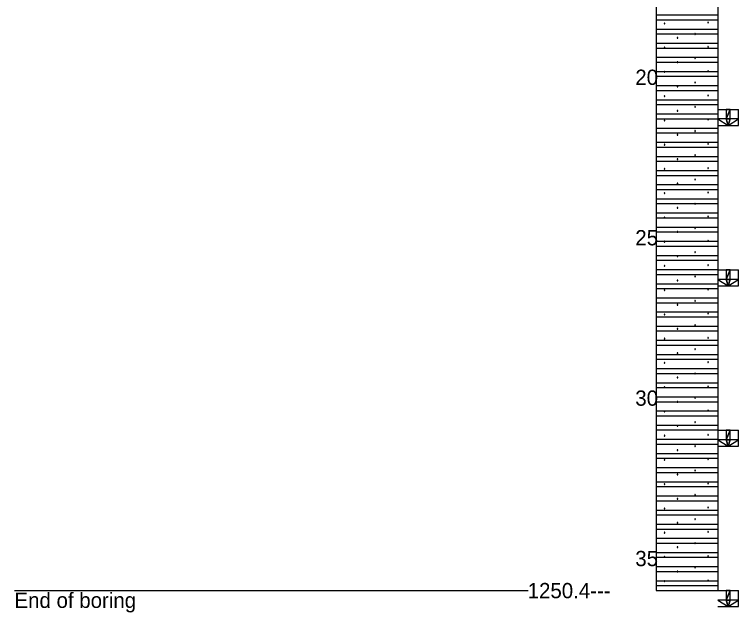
# Model space of a CAD drawing. Extents: x -2 to 138, y 24 to 58.
# Drawn here: x 27.88 to 33.76, y 39.39 to 44.24 of the extents above; entities that cross this region are included whole.
import ezdxf

# ---------------------------------------------------------------- set-up
doc = ezdxf.new("R2010")
doc.units = 0

msp = doc.modelspace()

# ---------------------------------------------------------------- linework, layer by layer
for points in [[(33.0889, 48.9382), (33.0889, 39.5632)], [(33.5889, 48.9382), (33.5889, 39.5632)], [(33.0889, 44.2363), (33.5889, 44.2363)], [(33.0889, 44.197), (33.5889, 44.197)], [(33.1593, 44.1672), (33.1577, 44.17), (33.1544, 44.17), (33.1528, 44.1672), (33.1544, 44.1643), (33.1577, 44.1643), (33.1593, 44.1672)], [(33.5121, 44.1737), (33.5104, 44.1766), (33.5072, 44.1766), (33.5055, 44.1737), (33.5072, 44.1709), (33.5104, 44.1709), (33.5121, 44.1737)], [(33.0889, 44.1215), (33.5889, 44.1215)], [(33.0889, 44.0821), (33.5889, 44.0821)], [(33.264, 44.0493), (33.2623, 44.0522), (33.2591, 44.0522), (33.2574, 44.0493), (33.2591, 44.0465), (33.2623, 44.0465), (33.264, 44.0493)], [(33.4066, 44.0812), (33.4049, 44.084), (33.4016, 44.084), (33.4, 44.0812), (33.4016, 44.0783), (33.4049, 44.0783), (33.4066, 44.0812)], [(33.0889, 44.0067), (33.5889, 44.0067)], [(33.5121, 43.9768), (33.5104, 43.9797), (33.5072, 43.9797), (33.5055, 43.9768), (33.5072, 43.974), (33.5104, 43.974), (33.5121, 43.9768)], [(33.0889, 43.9673), (33.5889, 43.9673)], [(33.1593, 43.9703), (33.1577, 43.9732), (33.1544, 43.9732), (33.1528, 43.9703), (33.1544, 43.9674), (33.1577, 43.9674), (33.1593, 43.9703)], [(33.0889, 43.8919), (33.5889, 43.8919)], [(33.4066, 43.8843), (33.4049, 43.8871), (33.4016, 43.8871), (33.4, 43.8843), (33.4016, 43.8815), (33.4049, 43.8815), (33.4066, 43.8843)], [(33.0889, 43.8525), (33.5889, 43.8525)], [(33.264, 43.8524), (33.2623, 43.8553), (33.2591, 43.8553), (33.2574, 43.8525), (33.2591, 43.8496), (33.2623, 43.8496), (33.264, 43.8524)], [(33.0889, 43.777), (33.5889, 43.777)], [(33.1593, 43.7735), (33.1577, 43.7763), (33.1544, 43.7763), (33.1528, 43.7735), (33.1544, 43.7706), (33.1577, 43.7706), (33.1593, 43.7735)], [(33.5121, 43.78), (33.5104, 43.7829), (33.5072, 43.7829), (33.5055, 43.78), (33.5072, 43.7772), (33.5104, 43.7772), (33.5121, 43.78)], [(33.0889, 43.7377), (33.5889, 43.7377)], [(33.4066, 43.6875), (33.4049, 43.6903), (33.4016, 43.6903), (33.4, 43.6875), (33.4016, 43.6846), (33.4049, 43.6846), (33.4066, 43.6875)], [(33.0889, 43.6622), (33.5889, 43.6622)], [(33.264, 43.6556), (33.2623, 43.6585), (33.2591, 43.6585), (33.2574, 43.6556), (33.2591, 43.6528), (33.2623, 43.6528), (33.264, 43.6556)], [(33.0889, 43.6228), (33.5889, 43.6228)], [(33.1593, 43.5766), (33.1577, 43.5795), (33.1544, 43.5795), (33.1528, 43.5766), (33.1544, 43.5737), (33.1577, 43.5737), (33.1593, 43.5766)], [(33.5121, 43.5831), (33.5104, 43.586), (33.5072, 43.586), (33.5055, 43.5831), (33.5072, 43.5803), (33.5104, 43.5803), (33.5121, 43.5831)], [(33.0889, 43.5474), (33.5889, 43.5474)], [(33.0889, 43.508), (33.5889, 43.508)], [(33.264, 43.4587), (33.2623, 43.4616), (33.2591, 43.4616), (33.2574, 43.4588), (33.2591, 43.4559), (33.2623, 43.4559), (33.264, 43.4587)], [(33.4066, 43.4906), (33.4049, 43.4934), (33.4016, 43.4934), (33.4, 43.4906), (33.4016, 43.4878), (33.4049, 43.4878), (33.4066, 43.4906)], [(33.5889, 43.4695), (33.7556, 43.4695)], [(33.7556, 43.3392), (33.7556, 43.4695)], [(33.0889, 43.4325), (33.5889, 43.4325)], [(33.0889, 43.3932), (33.5889, 43.3932)], [(33.1593, 43.3798), (33.1577, 43.3826), (33.1544, 43.3826), (33.1528, 43.3798), (33.1544, 43.3769), (33.1577, 43.3769), (33.1593, 43.3798)], [(33.5121, 43.3863), (33.5104, 43.3892), (33.5072, 43.3892), (33.5055, 43.3863), (33.5072, 43.3835), (33.5104, 43.3835), (33.5121, 43.3863)], [(33.5889, 43.3392), (33.7556, 43.3392)], [(33.0889, 43.3177), (33.5889, 43.3177)], [(33.0889, 43.2783), (33.5889, 43.2783)], [(33.4066, 43.2938), (33.4049, 43.2966), (33.4016, 43.2966), (33.4, 43.2938), (33.4016, 43.2909), (33.4049, 43.2909), (33.4066, 43.2938)], [(33.264, 43.2619), (33.2623, 43.2648), (33.2591, 43.2648), (33.2574, 43.2619), (33.2591, 43.2591), (33.2623, 43.2591), (33.264, 43.2619)], [(33.0889, 43.2029), (33.5889, 43.2029)], [(33.0889, 43.1635), (33.5889, 43.1635)], [(33.1593, 43.1829), (33.1577, 43.1858), (33.1544, 43.1858), (33.1528, 43.1829), (33.1544, 43.18), (33.1577, 43.18), (33.1593, 43.1829)], [(33.5121, 43.1894), (33.5104, 43.1923), (33.5072, 43.1923), (33.5055, 43.1894), (33.5072, 43.1866), (33.5104, 43.1866), (33.5121, 43.1894)], [(33.4066, 43.0969), (33.4049, 43.0997), (33.4016, 43.0997), (33.4, 43.0969), (33.4016, 43.0941), (33.4049, 43.0941), (33.4066, 43.0969)], [(33.0889, 43.0881), (33.5889, 43.0881)], [(33.0889, 43.0487), (33.5889, 43.0487)], [(33.264, 43.065), (33.2623, 43.0679), (33.2591, 43.0679), (33.2574, 43.0651), (33.2591, 43.0622), (33.2623, 43.0622), (33.264, 43.065)], [(33.1593, 42.9861), (33.1577, 42.9889), (33.1544, 42.9889), (33.1528, 42.9861), (33.1544, 42.9832), (33.1577, 42.9832), (33.1593, 42.9861)], [(33.5121, 42.9926), (33.5104, 42.9955), (33.5072, 42.9955), (33.5055, 42.9926), (33.5072, 42.9898), (33.5104, 42.9898), (33.5121, 42.9926)], [(33.0889, 42.9732), (33.5889, 42.9732)], [(33.0889, 42.9339), (33.5889, 42.9339)], [(33.264, 42.8682), (33.2623, 42.8711), (33.2591, 42.8711), (33.2574, 42.8682), (33.2591, 42.8653), (33.2623, 42.8653), (33.264, 42.8682)], [(33.4066, 42.9001), (33.4049, 42.9029), (33.4016, 42.9029), (33.4, 42.9001), (33.4016, 42.8972), (33.4049, 42.8972), (33.4066, 42.9001)], [(33.0889, 42.8584), (33.5889, 42.8584)], [(33.0889, 42.819), (33.5889, 42.819)], [(33.1593, 42.7892), (33.1577, 42.7921), (33.1544, 42.7921), (33.1528, 42.7892), (33.1544, 42.7863), (33.1577, 42.7863), (33.1593, 42.7892)], [(33.5121, 42.7957), (33.5104, 42.7986), (33.5072, 42.7986), (33.5055, 42.7957), (33.5072, 42.7929), (33.5104, 42.7929), (33.5121, 42.7957)], [(33.0889, 42.7436), (33.5889, 42.7436)], [(33.0889, 42.7042), (33.5889, 42.7042)], [(33.4066, 42.7032), (33.4049, 42.706), (33.4016, 42.706), (33.4, 42.7032), (33.4016, 42.7004), (33.4049, 42.7004), (33.4066, 42.7032)], [(33.264, 42.6713), (33.2623, 42.6742), (33.2591, 42.6742), (33.2574, 42.6714), (33.2591, 42.6685), (33.2623, 42.6685), (33.264, 42.6713)], [(33.0889, 42.6287), (33.5889, 42.6287)], [(33.0889, 42.5894), (33.5889, 42.5894)], [(33.1593, 42.5924), (33.1577, 42.5952), (33.1544, 42.5952), (33.1528, 42.5924), (33.1544, 42.5895), (33.1577, 42.5895), (33.1593, 42.5924)], [(33.5121, 42.5989), (33.5104, 42.6018), (33.5072, 42.6018), (33.5055, 42.5989), (33.5072, 42.5961), (33.5104, 42.5961), (33.5121, 42.5989)], [(33.0889, 42.5139), (33.5889, 42.5139)], [(33.0889, 42.4745), (33.5889, 42.4745)], [(33.264, 42.4745), (33.2623, 42.4774), (33.2591, 42.4774), (33.2574, 42.4745), (33.2591, 42.4716), (33.2623, 42.4716), (33.264, 42.4745)], [(33.4066, 42.5064), (33.4049, 42.5092), (33.4016, 42.5092), (33.4, 42.5064), (33.4016, 42.5035), (33.4049, 42.5035), (33.4066, 42.5064)], [(33.0889, 42.3991), (33.5889, 42.3991)], [(33.1593, 42.3955), (33.1577, 42.3984), (33.1544, 42.3984), (33.1528, 42.3955), (33.1544, 42.3926), (33.1577, 42.3926), (33.1593, 42.3955)], [(33.5121, 42.402), (33.5104, 42.4049), (33.5072, 42.4049), (33.5055, 42.402), (33.5072, 42.3992), (33.5104, 42.3992), (33.5121, 42.402)], [(33.0889, 42.3597), (33.5889, 42.3597)], [(33.0889, 42.2842), (33.5889, 42.2842)], [(33.264, 42.2776), (33.2623, 42.2805), (33.2591, 42.2805), (33.2574, 42.2777), (33.2591, 42.2748), (33.2623, 42.2748), (33.264, 42.2776)], [(33.4066, 42.3095), (33.4049, 42.3123), (33.4016, 42.3123), (33.4, 42.3095), (33.4016, 42.3067), (33.4049, 42.3067), (33.4066, 42.3095)], [(33.0889, 42.2449), (33.5889, 42.2449)], [(33.0889, 42.1694), (33.5889, 42.1694)], [(33.1593, 42.1987), (33.1577, 42.2015), (33.1544, 42.2015), (33.1528, 42.1987), (33.1544, 42.1958), (33.1577, 42.1958), (33.1593, 42.1987)], [(33.5121, 42.2052), (33.5104, 42.2081), (33.5072, 42.2081), (33.5055, 42.2052), (33.5072, 42.2024), (33.5104, 42.2024), (33.5121, 42.2052)], [(33.5889, 42.1674), (33.7556, 42.1674)], [(33.7556, 42.0372), (33.7556, 42.1674)], [(33.0889, 42.13), (33.5889, 42.13)], [(33.4066, 42.1127), (33.4049, 42.1155), (33.4016, 42.1155), (33.4, 42.1127), (33.4016, 42.1098), (33.4049, 42.1098), (33.4066, 42.1127)], [(33.0889, 42.0546), (33.5889, 42.0546)], [(33.264, 42.0808), (33.2623, 42.0837), (33.2591, 42.0837), (33.2574, 42.0808), (33.2591, 42.0779), (33.2623, 42.0779), (33.264, 42.0808)], [(33.0889, 42.0152), (33.5889, 42.0152)], [(33.1593, 42.0018), (33.1577, 42.0047), (33.1544, 42.0047), (33.1528, 42.0018), (33.1544, 41.9989), (33.1577, 41.9989), (33.1593, 42.0018)], [(33.5121, 42.0083), (33.5104, 42.0112), (33.5072, 42.0112), (33.5055, 42.0083), (33.5072, 42.0055), (33.5104, 42.0055), (33.5121, 42.0083)], [(33.5889, 42.0372), (33.7556, 42.0372)], [(33.0889, 41.9398), (33.5889, 41.9398)], [(33.0889, 41.9004), (33.5889, 41.9004)], [(33.264, 41.8839), (33.2623, 41.8868), (33.2591, 41.8868), (33.2574, 41.884), (33.2591, 41.8811), (33.2623, 41.8811), (33.264, 41.8839)], [(33.4066, 41.9158), (33.4049, 41.9186), (33.4016, 41.9186), (33.4, 41.9158), (33.4016, 41.913), (33.4049, 41.913), (33.4066, 41.9158)], [(33.0889, 41.8249), (33.5889, 41.8249)], [(33.1593, 41.805), (33.1577, 41.8078), (33.1544, 41.8078), (33.1528, 41.805), (33.1544, 41.8021), (33.1577, 41.8021), (33.1593, 41.805)], [(33.5121, 41.8115), (33.5104, 41.8144), (33.5072, 41.8144), (33.5055, 41.8115), (33.5072, 41.8087), (33.5104, 41.8087), (33.5121, 41.8115)], [(33.0889, 41.7856), (33.5889, 41.7856)], [(33.0889, 41.7101), (33.5889, 41.7101)], [(33.264, 41.6871), (33.2623, 41.69), (33.2591, 41.69), (33.2574, 41.6871), (33.2591, 41.6842), (33.2623, 41.6842), (33.264, 41.6871)], [(33.4066, 41.719), (33.4049, 41.7218), (33.4016, 41.7218), (33.4, 41.719), (33.4016, 41.7161), (33.4049, 41.7161), (33.4066, 41.719)], [(33.0889, 41.6707), (33.5889, 41.6707)], [(33.0889, 41.5953), (33.5889, 41.5953)], [(33.1593, 41.6081), (33.1577, 41.611), (33.1544, 41.611), (33.1528, 41.6081), (33.1544, 41.6052), (33.1577, 41.6052), (33.1593, 41.6081)], [(33.5121, 41.6146), (33.5104, 41.6175), (33.5072, 41.6175), (33.5055, 41.6146), (33.5072, 41.6118), (33.5104, 41.6118), (33.5121, 41.6146)], [(33.0889, 41.5559), (33.5889, 41.5559)], [(33.4066, 41.5221), (33.4049, 41.5249), (33.4016, 41.5249), (33.4, 41.5221), (33.4016, 41.5193), (33.4049, 41.5193), (33.4066, 41.5221)], [(33.0889, 41.4804), (33.5889, 41.4804)], [(33.264, 41.4902), (33.2623, 41.4931), (33.2591, 41.4931), (33.2574, 41.4903), (33.2591, 41.4874), (33.2623, 41.4874), (33.264, 41.4902)], [(33.0889, 41.4411), (33.5889, 41.4411)], [(33.1593, 41.4113), (33.1577, 41.4141), (33.1544, 41.4141), (33.1528, 41.4113), (33.1544, 41.4084), (33.1577, 41.4084), (33.1593, 41.4113)], [(33.5121, 41.4178), (33.5104, 41.4207), (33.5072, 41.4207), (33.5055, 41.4178), (33.5072, 41.415), (33.5104, 41.415), (33.5121, 41.4178)], [(33.0889, 41.3656), (33.5889, 41.3656)], [(33.0889, 41.3262), (33.5889, 41.3262)], [(33.264, 41.2934), (33.2623, 41.2963), (33.2591, 41.2963), (33.2574, 41.2934), (33.2591, 41.2905), (33.2623, 41.2905), (33.264, 41.2934)], [(33.4066, 41.3253), (33.4049, 41.3281), (33.4016, 41.3281), (33.4, 41.3253), (33.4016, 41.3224), (33.4049, 41.3224), (33.4066, 41.3253)], [(33.0889, 41.2508), (33.5889, 41.2508)], [(33.5121, 41.2209), (33.5104, 41.2238), (33.5072, 41.2238), (33.5055, 41.2209), (33.5072, 41.2181), (33.5104, 41.2181), (33.5121, 41.2209)], [(33.0889, 41.2114), (33.5889, 41.2114)], [(33.1593, 41.2144), (33.1577, 41.2173), (33.1544, 41.2173), (33.1528, 41.2144), (33.1544, 41.2115), (33.1577, 41.2115), (33.1593, 41.2144)], [(33.0889, 41.136), (33.5889, 41.136)], [(33.4066, 41.1284), (33.4049, 41.1312), (33.4016, 41.1312), (33.4, 41.1284), (33.4016, 41.1256), (33.4049, 41.1256), (33.4066, 41.1284)], [(33.0889, 41.0966), (33.5889, 41.0966)], [(33.264, 41.0965), (33.2623, 41.0994), (33.2591, 41.0994), (33.2574, 41.0966), (33.2591, 41.0937), (33.2623, 41.0937), (33.264, 41.0965)], [(33.0889, 41.0211), (33.5889, 41.0211)], [(33.1593, 41.0176), (33.1577, 41.0204), (33.1544, 41.0204), (33.1528, 41.0176), (33.1544, 41.0147), (33.1577, 41.0147), (33.1593, 41.0176)], [(33.5121, 41.0241), (33.5104, 41.027), (33.5072, 41.027), (33.5055, 41.0241), (33.5072, 41.0213), (33.5104, 41.0213), (33.5121, 41.0241)], [(33.0889, 40.9818), (33.5889, 40.9818)], [(33.4066, 40.9316), (33.4049, 40.9344), (33.4016, 40.9344), (33.4, 40.9316), (33.4016, 40.9287), (33.4049, 40.9287), (33.4066, 40.9316)], [(33.0889, 40.9063), (33.5889, 40.9063)], [(33.264, 40.8997), (33.2623, 40.9026), (33.2591, 40.9026), (33.2574, 40.8997), (33.2591, 40.8968), (33.2623, 40.8968), (33.264, 40.8997)], [(33.0889, 40.8669), (33.5889, 40.8669)], [(33.1593, 40.8207), (33.1577, 40.8236), (33.1544, 40.8236), (33.1528, 40.8207), (33.1544, 40.8178), (33.1577, 40.8178), (33.1593, 40.8207)], [(33.5121, 40.8272), (33.5104, 40.8301), (33.5072, 40.8301), (33.5055, 40.8272), (33.5072, 40.8244), (33.5104, 40.8244), (33.5121, 40.8272)], [(33.5889, 40.8653), (33.7556, 40.8653)], [(33.7556, 40.7351), (33.7556, 40.8653)], [(33.0889, 40.7915), (33.5889, 40.7915)], [(33.0889, 40.7521), (33.5889, 40.7521)], [(33.264, 40.7028), (33.2623, 40.7057), (33.2591, 40.7057), (33.2574, 40.7029), (33.2591, 40.7), (33.2623, 40.7), (33.264, 40.7028)], [(33.4066, 40.7347), (33.4049, 40.7375), (33.4016, 40.7375), (33.4, 40.7347), (33.4016, 40.7319), (33.4049, 40.7319), (33.4066, 40.7347)], [(33.5889, 40.7351), (33.7556, 40.7351)], [(33.0889, 40.6766), (33.5889, 40.6766)], [(33.0889, 40.6373), (33.5889, 40.6373)], [(33.5121, 40.6304), (33.5104, 40.6333), (33.5072, 40.6333), (33.5055, 40.6304), (33.5072, 40.6276), (33.5104, 40.6276), (33.5121, 40.6304)], [(33.1593, 40.6239), (33.1577, 40.6267), (33.1544, 40.6267), (33.1528, 40.6239), (33.1544, 40.621), (33.1577, 40.621), (33.1593, 40.6239)], [(33.0889, 40.5618), (33.5889, 40.5618)], [(33.0889, 40.5224), (33.5889, 40.5224)], [(33.4066, 40.5379), (33.4049, 40.5407), (33.4016, 40.5407), (33.4, 40.5379), (33.4016, 40.535), (33.4049, 40.535), (33.4066, 40.5379)], [(33.264, 40.506), (33.2623, 40.5089), (33.2591, 40.5089), (33.2574, 40.506), (33.2591, 40.5031), (33.2623, 40.5031), (33.264, 40.506)], [(33.0889, 40.447), (33.5889, 40.447)], [(33.0889, 40.4076), (33.5889, 40.4076)], [(33.1593, 40.427), (33.1577, 40.4299), (33.1544, 40.4299), (33.1528, 40.427), (33.1544, 40.4241), (33.1577, 40.4241), (33.1593, 40.427)], [(33.5121, 40.4335), (33.5104, 40.4364), (33.5072, 40.4364), (33.5055, 40.4335), (33.5072, 40.4307), (33.5104, 40.4307), (33.5121, 40.4335)], [(33.4066, 40.341), (33.4049, 40.3438), (33.4016, 40.3438), (33.4, 40.341), (33.4016, 40.3382), (33.4049, 40.3382), (33.4066, 40.341)], [(33.0889, 40.3321), (33.5889, 40.3321)], [(33.0889, 40.2928), (33.5889, 40.2928)], [(33.264, 40.3091), (33.2623, 40.312), (33.2591, 40.312), (33.2574, 40.3092), (33.2591, 40.3063), (33.2623, 40.3063), (33.264, 40.3091)], [(33.1593, 40.2302), (33.1577, 40.233), (33.1544, 40.233), (33.1528, 40.2302), (33.1544, 40.2273), (33.1577, 40.2273), (33.1593, 40.2302)], [(33.5121, 40.2367), (33.5104, 40.2396), (33.5072, 40.2396), (33.5055, 40.2367), (33.5072, 40.2339), (33.5104, 40.2339), (33.5121, 40.2367)], [(33.0889, 40.2173), (33.5889, 40.2173)], [(33.0889, 40.1779), (33.5889, 40.1779)], [(33.264, 40.1123), (33.2623, 40.1152), (33.2591, 40.1152), (33.2574, 40.1123), (33.2591, 40.1094), (33.2623, 40.1094), (33.264, 40.1123)], [(33.4066, 40.1442), (33.4049, 40.147), (33.4016, 40.147), (33.4, 40.1442), (33.4016, 40.1413), (33.4049, 40.1413), (33.4066, 40.1442)], [(33.0889, 40.1025), (33.5889, 40.1025)], [(33.0889, 40.0631), (33.5889, 40.0631)], [(33.0889, 39.9877), (33.5889, 39.9877)], [(33.1593, 40.0333), (33.1577, 40.0362), (33.1544, 40.0362), (33.1528, 40.0333), (33.1544, 40.0304), (33.1577, 40.0304), (33.1593, 40.0333)], [(33.5121, 40.0398), (33.5104, 40.0427), (33.5072, 40.0427), (33.5055, 40.0398), (33.5072, 40.037), (33.5104, 40.037), (33.5121, 40.0398)], [(33.0889, 39.9483), (33.5889, 39.9483)], [(33.4066, 39.9473), (33.4049, 39.9501), (33.4016, 39.9501), (33.4, 39.9473), (33.4016, 39.9445), (33.4049, 39.9445), (33.4066, 39.9473)], [(33.0889, 39.8728), (33.5889, 39.8728)], [(33.264, 39.9154), (33.2623, 39.9183), (33.2591, 39.9183), (33.2574, 39.9155), (33.2591, 39.9126), (33.2623, 39.9126), (33.264, 39.9154)], [(33.0889, 39.8335), (33.5889, 39.8335)], [(33.1593, 39.8365), (33.1577, 39.8393), (33.1544, 39.8393), (33.1528, 39.8365), (33.1544, 39.8336), (33.1577, 39.8336), (33.1593, 39.8365)], [(33.5121, 39.843), (33.5104, 39.8459), (33.5072, 39.8459), (33.5055, 39.843), (33.5072, 39.8402), (33.5104, 39.8402), (33.5121, 39.843)], [(33.0889, 39.758), (33.5889, 39.758)], [(33.4066, 39.7505), (33.4049, 39.7533), (33.4016, 39.7533), (33.4, 39.7505), (33.4016, 39.7476), (33.4049, 39.7476), (33.4066, 39.7505)], [(33.0889, 39.7186), (33.5889, 39.7186)], [(33.264, 39.7186), (33.2623, 39.7215), (33.2591, 39.7215), (33.2574, 39.7186), (33.2591, 39.7157), (33.2623, 39.7157), (33.264, 39.7186)], [(33.0889, 39.6432), (33.5889, 39.6432)], [(33.1593, 39.6396), (33.1577, 39.6424), (33.1544, 39.6424), (33.1528, 39.6396), (33.1544, 39.6367), (33.1577, 39.6367), (33.1593, 39.6396)], [(33.5121, 39.6461), (33.5104, 39.649), (33.5072, 39.649), (33.5055, 39.6461), (33.5072, 39.6433), (33.5104, 39.6433), (33.5121, 39.6461)], [(33.0889, 39.6038), (33.5889, 39.6038)], [(27.8838, 39.5632), (32.0505, 39.5632)], [(33.0889, 39.5632), (33.5889, 39.5632)], [(33.5889, 39.5632), (33.7556, 39.5632)], [(33.7556, 39.433), (33.7556, 39.5632)], [(33.5889, 39.433), (33.7556, 39.433)]]:
    msp.add_lwpolyline(points)
for points in [[(33.6556, 43.3913), (33.6889, 43.3913), (33.6889, 43.4695), (33.6556, 43.3913)], [(33.6556, 43.3913), (33.6889, 43.4695), (33.6556, 43.4695), (33.6556, 43.3913)], [(33.6556, 43.3913), (33.5889, 43.3913), (33.6722, 43.3392), (33.6556, 43.3913)], [(33.6556, 43.3913), (33.6722, 43.3392), (33.6889, 43.3913), (33.6556, 43.3913)], [(33.6722, 43.3392), (33.7556, 43.3913), (33.6889, 43.3913), (33.6722, 43.3392)], [(33.6556, 42.0892), (33.6889, 42.0892), (33.6889, 42.1674), (33.6556, 42.0892)], [(33.6556, 42.0892), (33.6889, 42.1674), (33.6556, 42.1674), (33.6556, 42.0892)], [(33.6556, 42.0892), (33.5889, 42.0892), (33.6722, 42.0372), (33.6556, 42.0892)], [(33.6556, 42.0892), (33.6722, 42.0372), (33.6889, 42.0892), (33.6556, 42.0892)], [(33.6722, 42.0372), (33.7556, 42.0892), (33.6889, 42.0892), (33.6722, 42.0372)], [(33.6556, 40.7872), (33.6889, 40.7872), (33.6889, 40.8653), (33.6556, 40.7872)], [(33.6556, 40.7872), (33.6889, 40.8653), (33.6556, 40.8653), (33.6556, 40.7872)], [(33.6556, 40.7872), (33.5889, 40.7872), (33.6722, 40.7351), (33.6556, 40.7872)], [(33.6556, 40.7872), (33.6722, 40.7351), (33.6889, 40.7872), (33.6556, 40.7872)], [(33.6722, 40.7351), (33.7556, 40.7872), (33.6889, 40.7872), (33.6722, 40.7351)], [(33.6556, 39.4851), (33.6889, 39.4851), (33.6889, 39.5632), (33.6556, 39.4851)], [(33.6556, 39.4851), (33.6889, 39.5632), (33.6556, 39.5632), (33.6556, 39.4851)], [(33.6556, 39.4851), (33.5889, 39.4851), (33.6722, 39.433), (33.6556, 39.4851)], [(33.6556, 39.4851), (33.6722, 39.433), (33.6889, 39.4851), (33.6556, 39.4851)], [(33.6722, 39.433), (33.7556, 39.4851), (33.6889, 39.4851), (33.6722, 39.433)]]:
    msp.add_lwpolyline(points, close=True)

# ---------------------------------------------------------------- texts
for s, p in [('20', (32.9185, 43.6679)), ('25', (32.9185, 42.3658)), ('30', (32.9185, 41.0637)), ('35', (32.9185, 39.7616)), ('1250.4---', (32.0456, 39.5012)), ('End of boring', (27.8838, 39.4225))]:
    msp.add_text(s, height=0.124).set_placement(p)

doc.saveas('drawing.dxf')
